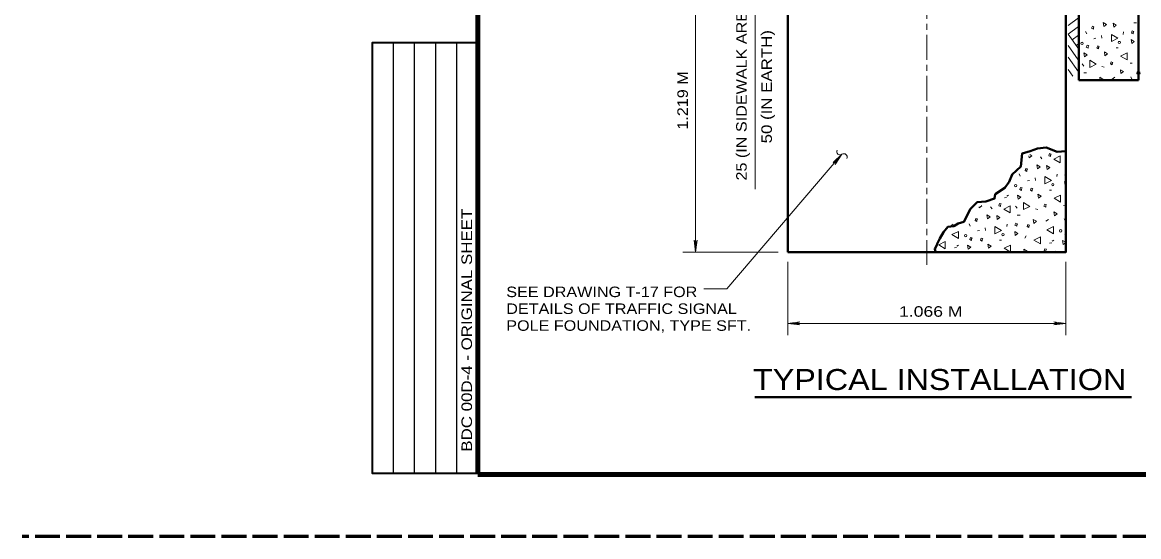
# Model space of a CAD drawing. Extents: x 312583 to 312853, y 144419 to 144586.
# Drawn here: x 312583.5 to 312664.4, y 144418.6 to 144455.8 of the extents above; entities that cross this region are included whole.
import ezdxf
from ezdxf.enums import TextEntityAlignment as Align

# ---------------------------------------------------------------- set-up
doc = ezdxf.new("R2010")
doc.units = 0
doc.header["$LTSCALE"] = 0.3
doc.header["$PDMODE"] = 32
doc.header["$PDSIZE"] = 0.15
doc.linetypes.add('LONG_DASH_SHORT_DASH', pattern=[9.9, 6, -1.2, 1.5, -1.2])
doc.linetypes.add('LONG_DASHED', pattern=[7.5, 6, -1.5])
for name, color, linetype, lineweight in [('1', 7, 'Continuous', 40), ('2', 7, 'Continuous', 13), ('63', 7, 'LONG_DASHED', 60)]:
    doc.layers.add(name, color=color, linetype=linetype, lineweight=lineweight)

msp = doc.modelspace()

# ---------------------------------------------------------------- linework, layer by layer
at = {"layer": '1'}
for p, q in [((312660.0274, 144451.6263), (312660.0274, 144461.2096)), ((312664.3438, 144456.4179), (312664.3438, 144451.6263)), ((312660.0274, 144451.6263), (312664.3438, 144451.6263))]:
    msp.add_line(p, q, dxfattribs=at)
at = {"layer": '1', "lineweight": 13}
for p, q in [((312663.9911, 144455.7663), (312664.1981, 144455.7816)), ((312660.5028, 144455.1529), (312660.5871, 144454.9843)), ((312661.1084, 144454.6239), (312661.2541, 144454.6699)), ((312661.6681, 144454.8616), (312661.6911, 144454.6546)), ((312663.2321, 144454.9383), (312663.2551, 144455.1223)), ((312662.7184, 144453.9569), (312662.8641, 144453.9646)), ((312660.2574, 144452.8069), (312660.3801, 144452.6459)), ((312663.7304, 144452.8529), (312663.8838, 144452.8683)), ((312660.3724, 144452.1476), (312660.5794, 144452.1629)), ((312661.6834, 144452.6076), (312661.8598, 144452.5693)), ((312662.6188, 144451.8409), (312662.4424, 144451.7029)), ((312663.7764, 144451.8793), (312663.8608, 144451.7106))]:
    msp.add_line(p, q, dxfattribs=at)
at = {"layer": '1', "lineweight": 25}
for p, q in [((312610.4087, 144423.1446), (312610.4087, 144454.3629)), ((312611.9315, 144423.1446), (312611.9315, 144454.3629)), ((312613.4545, 144423.1446), (312613.4545, 144454.3629)), ((312614.9772, 144423.1446), (312614.9772, 144454.3629))]:
    msp.add_line(p, q, dxfattribs=at)
at = {"layer": '1', "lineweight": 158}
msp.add_line((312616.5, 144423.0846), (312849, 144423.0846), dxfattribs=at)
msp.add_lwpolyline([(312616.5, 144423.1446), (312616.5, 144585.0846), (312849, 144585.0846)], dxfattribs=at)
at = {"layer": '1'}
for points in [[(312638.9441, 144439.1679), (312659.0691, 144439.1679), (312659.0691, 144456.4179)], [(312638.9441, 144439.1679), (312638.9441, 144456.4179), (312659.0691, 144456.4179)], [(312659.0768, 144446.4819), (312658.4481, 144446.4283), (312657.6584, 144446.7426), (312657.0221, 144446.6889), (312656.4931, 144446.4819), (312655.9181, 144446.3209), (312655.8108, 144445.3703), (312655.1821, 144444.7953), (312654.9674, 144444.2663), (312654.6531, 144443.8446), (312653.9631, 144443.3693), (312653.9171, 144443.0549), (312653.2808, 144442.8403), (312652.6521, 144442.7866), (312652.2304, 144442.3649), (312652.1768, 144442.3113), (312651.7014, 144441.3683), (312651.2798, 144441.2609), (312650.9654, 144441.0539), (312650.5438, 144441.0003), (312650.2218, 144440.6323), (312649.9611, 144440.1569), (312649.7541, 144439.7889), (312649.7541, 144439.7353), (312649.5931, 144439.4133), (312649.6468, 144439.2063)]]:
    msp.add_lwpolyline(points, dxfattribs=at)
at = {"layer": '1', "lineweight": 13}
for points in [[(312661.0701, 144455.4136), (312661.1161, 144455.4979), (312661.0011, 144455.5363), (312660.9398, 144455.3829), (312661.0701, 144455.3139)], [(312661.8368, 144455.5056), (312662.0284, 144455.6513), (312661.7908, 144455.7893)], [(312662.5421, 144455.4596), (312662.7338, 144455.6129), (312662.4961, 144455.7509)], [(312663.9604, 144455.0763), (312664.0064, 144455.1529), (312663.8914, 144455.1913), (312663.8301, 144455.0379), (312663.9604, 144454.9689)], [(312662.3811, 144454.9383), (312662.3811, 144454.4246), (312662.8488, 144454.6546)], [(312663.8454, 144454.2866), (312664.0371, 144454.4323), (312663.7994, 144454.5779)], [(312660.4338, 144453.3053), (312660.6254, 144453.4509), (312660.3878, 144453.5966)], [(312660.6868, 144454.0413), (312660.7328, 144454.1256), (312660.6178, 144454.1563), (312660.5564, 144454.0106), (312660.6868, 144453.9339)], [(312661.4534, 144453.9876), (312661.4994, 144454.0719), (312661.3844, 144454.1103), (312661.3231, 144453.9569), (312661.4534, 144453.8879)], [(312661.9058, 144453.3819), (312662.1051, 144453.5276), (312661.8674, 144453.6656)], [(312663.5158, 144453.0906), (312663.5158, 144453.6043), (312663.0481, 144453.3743)], [(312660.8248, 144453.0676), (312660.8248, 144452.5463), (312661.2848, 144452.7839)], [(312662.4348, 144452.8299), (312662.4808, 144452.9143), (312662.3658, 144452.9526), (312662.3044, 144452.7993), (312662.4348, 144452.7303)], [(312663.0711, 144452.1016), (312663.2628, 144452.2473), (312663.0328, 144452.3853)]]:
    msp.add_lwpolyline(points, close=True, dxfattribs=at)
at = {"layer": '1', "lineweight": 35}
msp.add_lwpolyline([(312616.5, 144423.1446), (312608.8858, 144423.1446), (312608.8858, 144454.3629), (312616.5, 144454.3629)], dxfattribs=at)
at = {"layer": '1', "lineweight": 13}
for points in [[(312664.3438, 144452.2396), (312664.2671, 144452.2626), (312664.2134, 144452.1093), (312664.3438, 144452.0403), (312664.3438, 144452.1476)], [(312661.6604, 144451.6263), (312661.7601, 144451.7029), (312661.5301, 144451.8486), (312661.5608, 144451.6263)]]:
    msp.add_lwpolyline(points, dxfattribs=at)
for centre, radius in [((312660.2553, 144454.2876), 0.0865), ((312662.9549, 144454.3582), 0.0784)]:
    msp.add_circle(centre, radius, dxfattribs=at)
at = {"layer": '1'}
msp.add_point((312664.3438, 144452.1476), dxfattribs=at)
at = {"layer": '2', "linetype": 'LONG_DASH_SHORT_DASH'}
msp.add_line((312649.0104, 144438.2556), (312649.0104, 144579.5523), dxfattribs=at)
at = {"layer": '2'}
for p, q in [((312632.2664, 144439.1679), (312632.2664, 144461.2096)), ((312660.0044, 144456.1343), (312659.2378, 144455.5899)), ((312660.0044, 144455.5056), (312659.2378, 144454.9613)), ((312659.2378, 144454.9613), (312660.0121, 144453.8803)), ((312660.0044, 144454.8769), (312659.5368, 144454.5473)), ((312659.2378, 144454.1333), (312659.9814, 144453.0906)), ((312660.0044, 144454.2483), (312659.8358, 144454.1333)), ((312659.2378, 144453.2899), (312660.0044, 144452.2243)), ((312659.2378, 144452.4083), (312659.5904, 144451.9253)), ((312634.5434, 144436.5229), (312642.8694, 144446.2596)), ((312642.8694, 144446.2596), (312642.2254, 144445.6769)), ((312642.2254, 144445.6769), (312642.4861, 144445.8149)), ((312642.8694, 144446.2596), (312642.3864, 144445.5313)), ((312642.3864, 144445.5313), (312642.4861, 144445.8149)), ((312656.4011, 144446.1599), (312656.4241, 144446.0066)), ((312657.2444, 144446.0679), (312657.3518, 144445.9299)), ((312659.0614, 144446.1293), (312659.0691, 144446.1139)), ((312655.6881, 144444.8566), (312655.7724, 144444.6879)), ((312658.4174, 144444.6419), (312658.4404, 144444.8259)), ((312656.2938, 144444.3353), (312656.4394, 144444.3736)), ((312656.8534, 144444.5653), (312656.8764, 144444.3583)), ((312659.0308, 144443.9903), (312659.0691, 144444.0286)), ((312654.6378, 144443.1009), (312654.7834, 144443.1316)), ((312654.8064, 144443.2389), (312654.9368, 144443.3079)), ((312657.9038, 144443.6606), (312658.0494, 144443.6683)), ((312652.7978, 144442.4646), (312652.8054, 144442.3879)), ((312653.6334, 144442.4493), (312653.7331, 144442.3113)), ((312655.4428, 144442.5106), (312655.5654, 144442.3496)), ((312656.8764, 144442.3189), (312657.0451, 144442.2729)), ((312655.5578, 144441.8513), (312655.7724, 144441.8666)), ((312657.8118, 144441.5446), (312657.6278, 144441.4143)), ((312658.9618, 144441.5829), (312659.0461, 144441.4143)), ((312650.9194, 144441.1996), (312650.7354, 144441.0693)), ((312652.0694, 144441.2379), (312652.1538, 144441.0693)), ((312652.6751, 144440.7166), (312652.8208, 144440.7549)), ((312653.2348, 144440.9466), (312653.2578, 144440.7396)), ((312654.7988, 144441.0233), (312654.8218, 144441.2149)), ((312632.1591, 144440.0343), (312632.2664, 144439.7583)), ((312632.2664, 144439.1679), (312632.1591, 144440.0343)), ((312632.3738, 144440.0343), (312632.2664, 144439.7583)), ((312632.2664, 144439.1679), (312632.3738, 144440.0343)), ((312654.2851, 144440.0419), (312654.4308, 144440.0496)), ((312656.1941, 144440.3639), (312656.1174, 144440.1953)), ((312657.9038, 144439.8349), (312658.0571, 144439.8579)), ((312658.0801, 144439.9653), (312658.2028, 144440.0343)), ((312658.8851, 144439.7353), (312659.0691, 144439.8733)), ((312638.2541, 144439.1679), (312631.3388, 144439.1679)), ((312651.0191, 144439.4899), (312651.1648, 144439.5129)), ((312651.1878, 144439.6203), (312651.3181, 144439.6893)), ((312658.7164, 144439.2369), (312658.7624, 144439.1756)), ((312638.9441, 144433.1573), (312638.9441, 144438.4779)), ((312659.0691, 144433.1573), (312659.0691, 144438.4779)), ((312634.5434, 144436.5229), (312632.8797, 144436.5229)), ((312638.9441, 144434.0236), (312639.8104, 144434.1309)), ((312659.0691, 144434.0236), (312638.9441, 144434.0236)), ((312638.9441, 144434.0236), (312639.8104, 144433.9163)), ((312639.8104, 144434.1309), (312639.5344, 144434.0236)), ((312639.8104, 144433.9163), (312639.5344, 144434.0236)), ((312658.2028, 144434.1309), (312658.4788, 144434.0236)), ((312659.0691, 144434.0236), (312658.2028, 144434.1309)), ((312658.2028, 144433.9163), (312658.4788, 144434.0236)), ((312659.0691, 144434.0236), (312658.2028, 144433.9163))]:
    msp.add_line(p, q, dxfattribs=at)
at = {"layer": '2', "lineweight": 40}
msp.add_line((312636.5499, 144428.6799), (312663.8339, 144428.6799), dxfattribs=at)
at = {"layer": '2'}
for points in [[(312636.5751, 144443.7373), (312636.5751, 144461.2096), (312636.5751, 144462.1679)], [(312656.4241, 144446.0066), (312656.6158, 144446.1523), (312656.4701, 144446.2366)], [(312659.0691, 144444.8796), (312659.0154, 144444.7416), (312659.0691, 144444.7109)], [(312659.0691, 144444.2279), (312658.9848, 144444.2816), (312659.0308, 144443.9903)], [(312652.8054, 144442.3879), (312652.9971, 144442.5336), (312652.9588, 144442.5566)], [(312658.9158, 144442.5643), (312659.0691, 144442.5719), (312659.0691, 144442.5719)], [(312659.0691, 144439.8886), (312658.8468, 144440.0266), (312658.8851, 144439.7353)], [(312659.0691, 144440.5786), (312659.0154, 144440.4406), (312659.0691, 144440.4099)], [(312655.0824, 144439.2063), (312655.0824, 144439.6893), (312654.6148, 144439.4593), (312655.0364, 144439.2063)], [(312656.1864, 144439.1986), (312656.2708, 144439.2599), (312656.0408, 144439.3979), (312656.0638, 144439.1986)], [(312658.3254, 144439.1756), (312658.3254, 144439.2523), (312658.1798, 144439.1756)]]:
    msp.add_lwpolyline(points, dxfattribs=at)
for points in [[(312657.9728, 144446.1983), (312658.0188, 144446.2749), (312657.9038, 144446.3133), (312657.8424, 144446.1599), (312657.9728, 144446.0909)], [(312657.0221, 144445.2093), (312657.2138, 144445.3549), (312656.9761, 144445.4929)], [(312658.6704, 144445.6309), (312658.6704, 144446.1446), (312658.2028, 144445.9069)], [(312656.2554, 144445.1249), (312656.3014, 144445.2016), (312656.1864, 144445.2399), (312656.1251, 144445.0866), (312656.2554, 144445.0176)], [(312657.7274, 144445.1709), (312657.9191, 144445.3166), (312657.6891, 144445.4546)], [(312655.8721, 144443.7449), (312655.9181, 144443.8293), (312655.8031, 144443.8676), (312655.7418, 144443.7143), (312655.8721, 144443.6453)], [(312657.5664, 144444.6419), (312657.5664, 144444.1283), (312658.0341, 144444.3659)], [(312655.6191, 144443.0089), (312655.8108, 144443.1546), (312655.5731, 144443.3003)], [(312656.6388, 144443.6989), (312656.6848, 144443.7756), (312656.5698, 144443.8139), (312656.5084, 144443.6606), (312656.6388, 144443.5916)], [(312657.0911, 144443.0856), (312657.2904, 144443.2313), (312657.0528, 144443.3769)], [(312658.7011, 144442.7943), (312658.7011, 144443.3079), (312658.2334, 144443.0779)], [(312654.3541, 144442.5796), (312654.4001, 144442.6639), (312654.2851, 144442.6946), (312654.2238, 144442.5413), (312654.3541, 144442.4723)], [(312655.0594, 144442.0123), (312655.0594, 144442.5259), (312654.5918, 144442.2959)], [(312656.0101, 144442.7713), (312656.0101, 144442.2576), (312656.4701, 144442.4876)], [(312657.6201, 144442.5413), (312657.6661, 144442.6179), (312657.5511, 144442.6563), (312657.4898, 144442.5029), (312657.6201, 144442.4339)], [(312652.6368, 144441.5063), (312652.6828, 144441.5829), (312652.5678, 144441.6213), (312652.5064, 144441.4679), (312652.6368, 144441.3989)], [(312653.4034, 144441.5906), (312653.5951, 144441.7363), (312653.3651, 144441.8743)], [(312654.1088, 144441.5523), (312654.3004, 144441.6979), (312654.0704, 144441.8359)], [(312656.7538, 144441.2609), (312656.9454, 144441.4143), (312656.7154, 144441.5523)], [(312658.2564, 144441.8053), (312658.4481, 144441.9509), (312658.2181, 144442.0966)], [(312651.2951, 144440.1646), (312651.2951, 144440.6783), (312650.8274, 144440.4483)], [(312653.9478, 144441.0233), (312653.9478, 144440.5096), (312654.4154, 144440.7473)], [(312655.4121, 144440.3793), (312655.6038, 144440.5249), (312655.3738, 144440.6629)], [(312655.5271, 144441.1613), (312655.5731, 144441.2379), (312655.4581, 144441.2763), (312655.3968, 144441.1229), (312655.5271, 144441.0539)], [(312656.4011, 144441.0616), (312656.4471, 144441.1383), (312656.3321, 144441.1766), (312656.2708, 144441.0233), (312656.4011, 144440.9543)], [(312658.1798, 144440.5096), (312658.1798, 144441.0233), (312657.7121, 144440.7933)], [(312650.3444, 144439.4286), (312650.3444, 144439.9423), (312649.8768, 144439.7123)], [(312652.2534, 144440.1339), (312652.2994, 144440.2106), (312652.1844, 144440.2489), (312652.1308, 144440.0956), (312652.2534, 144440.0266)], [(312653.0201, 144440.0803), (312653.0661, 144440.1569), (312652.9511, 144440.1953), (312652.8898, 144440.0419), (312653.0201, 144439.9729)], [(312657.2368, 144439.7736), (312657.2368, 144440.2873), (312656.7691, 144440.0573)], [(312652.0004, 144439.3903), (312652.1921, 144439.5436), (312651.9544, 144439.6816)], [(312653.4801, 144439.4669), (312653.6718, 144439.6203), (312653.4341, 144439.7583)], [(312657.6278, 144439.3059), (312657.6738, 144439.3903), (312657.5588, 144439.4209), (312657.4974, 144439.2753), (312657.6278, 144439.1986)]]:
    msp.add_lwpolyline(points, close=True, dxfattribs=at)
for centre, radius in [((312655.4412, 144443.9925), 0.0865), ((312658.1407, 144444.0631), 0.0784), ((312658.7136, 144440.7202), 0.0865), ((312651.8239, 144440.3752), 0.0865), ((312654.5235, 144440.4459), 0.0784)]:
    msp.add_circle(centre, radius, dxfattribs=at)
for centre, start, end in [((312642.731, 144446.4599), 154.47542, 304.47542), ((312643.0021, 144446.0651), 334.47542, 124.47542)]:
    msp.add_arc(centre, 0.2395, start, end, dxfattribs=at)
at = {"layer": '63'}
msp.add_line((312851.75, 144418.5846), (312583.526, 144418.5846), dxfattribs=at)

# ---------------------------------------------------------------- texts
at = {"layer": '1', "width": 1.2}
msp.add_text('BDC 00D-4 - ORIGINAL SHEET', height=0.7614, rotation=90, dxfattribs=at).set_placement((312616.0832, 144424.7374))
at = {"layer": '2'}
for s, width, p in [('25 (IN SIDEWALK AREA)', 1.15, (312635.9709, 144444.362)), ('50 (IN EARTH)', 1.2, (312637.7951, 144447.0519)), ('1.219 M', 1.15, (312631.716, 144448.0421))]:
    msp.add_text(s, height=0.76, rotation=90, dxfattribs=dict(at, width=width)).set_placement(p)
for s, width, p in [('SEE DRAWING T-17 FOR', 1.15, (312618.5659, 144435.9239)), ('DETAILS OF TRAFFIC SIGNAL', 1.15, (312618.5659, 144434.7039)), ('1.066 M', 1.25, (312647.0061, 144434.5037)), ('POLE FOUNDATION, TYPE SFT.', 1.15, (312618.5659, 144433.4839))]:
    msp.add_text(s, height=0.76, dxfattribs=dict(at, width=width)).set_placement(p)
at = {"layer": '2', "width": 1.15}
msp.add_text('TYPICAL INSTALLATION', height=1.52, dxfattribs=at).set_placement((312649.9405, 144429.1975), align=Align.CENTER)

doc.saveas('drawing.dxf')
